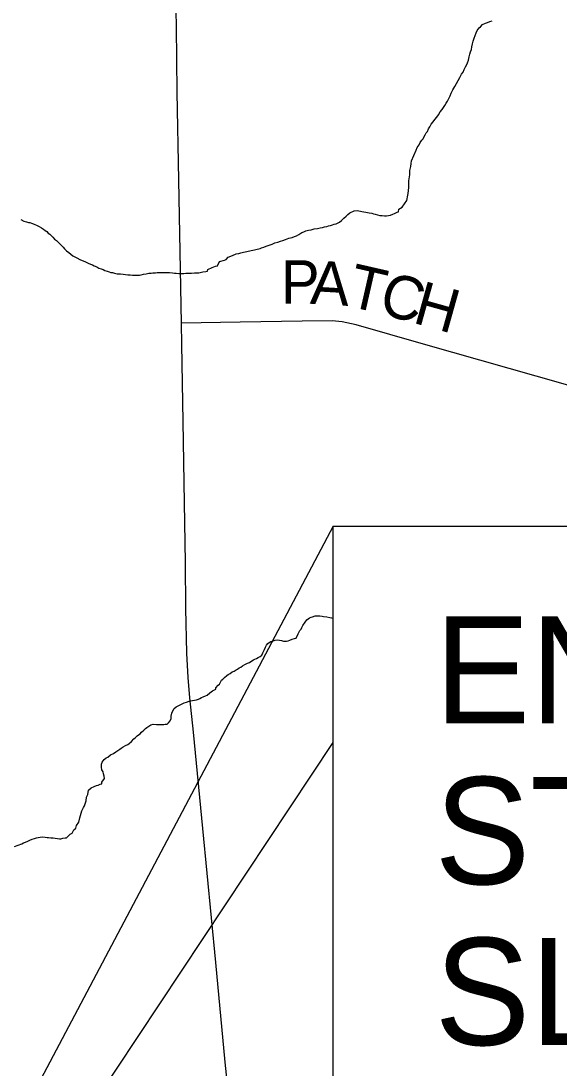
# Model space of a CAD drawing. Extents: x 0 to 34, y 0 to 22.
# Drawn here: x 6.59 to 7.293, y 17.696 to 19.063 of the extents above; entities that cross this region are included whole.
import ezdxf

# ---------------------------------------------------------------- set-up
doc = ezdxf.new("R2010")
doc.units = 0
for name, color, linetype in [('GM_X_Minor_River', 7, 'Continuous'), ('GM_X_State_Route', 7, 'Continuous'), ('GM_X_Township_Road', 7, 'Continuous'), ('GM_X_Township_Road_Text', 7, 'Continuous'), ('SH_Border', 7, 'Continuous'), ('SH_Text', 7, 'Continuous')]:
    doc.layers.add(name, color=color, linetype=linetype)

msp = doc.modelspace()

# ---------------------------------------------------------------- linework, layer by layer
at = {"layer": 'GM_X_Minor_River'}
for points in [[(7.1, 18.8803), (7.1062, 18.8941), (7.1076, 18.8976), (7.1102, 18.9014), (7.1116, 18.9041), (7.1135, 18.9072), (7.1153, 18.9091), (7.1164, 18.9114), (7.1179, 18.9141), (7.1194, 18.9168), (7.1208, 18.9187), (7.1223, 18.9222), (7.1241, 18.9249), (7.126, 18.928), (7.1282, 18.9311), (7.1304, 18.9342), (7.133, 18.9373), (7.1352, 18.9403), (7.1374, 18.9442), (7.14, 18.9473), (7.1419, 18.95), (7.1437, 18.9527), (7.1452, 18.9554), (7.147, 18.9581), (7.1485, 18.9608), (7.1507, 18.9654), (7.1521, 18.9688), (7.1543, 18.9731), (7.1565, 18.9773), (7.1591, 18.9811), (7.1609, 18.985), (7.1631, 18.9892), (7.1653, 18.9934), (7.1675, 18.9961), (7.169, 18.9996), (7.1708, 19.0031), (7.1722, 19.0061), (7.1733, 19.0084), (7.1744, 19.0119), (7.1755, 19.0161), (7.1765, 19.0195), (7.1772, 19.0226), (7.1783, 19.0256), (7.179, 19.0291), (7.18, 19.0333), (7.1807, 19.0367), (7.1818, 19.0405), (7.1847, 19.0474), (7.1861, 19.0505), (7.1883, 19.054), (7.1902, 19.0555), (7.1928, 19.0583), (7.197, 19.0602), (7.1996, 19.0611), (7.2026, 19.0623), (7.2056, 19.0631)], [(6.8052, 18.7337), (6.809, 18.7338), (6.8128, 18.7338), (6.8163, 18.7339), (6.8197, 18.734), (6.822, 18.734), (6.8273, 18.7353), (6.8314, 18.7358), (6.8333, 18.7362), (6.8341, 18.7385), (6.8397, 18.7409), (6.8438, 18.7429), (6.8465, 18.7433), (6.8494, 18.7487), (6.8555, 18.7507), (6.8577, 18.7515), (6.8607, 18.7543), (6.866, 18.7566), (6.8709, 18.7587), (6.8743, 18.7595), (6.877, 18.7603), (6.8804, 18.7611), (6.8826, 18.7616), (6.8887, 18.7628), (6.8906, 18.7633), (6.8929, 18.7637), (6.8951, 18.7641), (6.8985, 18.765), (6.9004, 18.7654), (6.9023, 18.7658), (6.9042, 18.7666), (6.9069, 18.7674), (6.9102, 18.769), (6.914, 18.7702), (6.9178, 18.7715), (6.9216, 18.7731), (6.9253, 18.7743), (6.9287, 18.7755), (6.9318, 18.7763), (6.9355, 18.7775), (6.9397, 18.7792), (6.9442, 18.7804), (6.9473, 18.7816), (6.9499, 18.7824), (6.9529, 18.784), (6.9567, 18.7867), (6.9593, 18.7876), (6.9619, 18.7888), (6.9653, 18.7896), (6.9691, 18.7904), (6.9729, 18.7917), (6.9771, 18.7921), (6.9809, 18.793), (6.9839, 18.7934), (6.9865, 18.7942), (6.9896, 18.7947), (6.9918, 18.7955), (6.9941, 18.7959), (6.9968, 18.7967), (6.999, 18.7975), (7.0017, 18.798), (7.0036, 18.7988), (7.0062, 18.8004), (7.0088, 18.8023), (7.0118, 18.8054), (7.0148, 18.8081), (7.017, 18.8101), (7.0196, 18.8124), (7.0253, 18.8148), (7.0295, 18.8153), (7.0352, 18.8143), (7.0402, 18.8132), (7.0447, 18.8126), (7.0482, 18.8119), (7.0505, 18.8112), (7.0528, 18.8105), (7.0555, 18.8098), (7.0585, 18.8091), (7.0616, 18.8088), (7.0646, 18.8085), (7.0673, 18.8085), (7.0699, 18.809), (7.0726, 18.8094), (7.0756, 18.8106), (7.0779, 18.8114), (7.0812, 18.8134), (7.0831, 18.8138), (7.0834, 18.8172), (7.0879, 18.82), (7.0939, 18.8285), (7.0952, 18.8353), (7.0959, 18.8376), (7.0965, 18.8453), (7.0968, 18.8494), (7.0967, 18.854), (7.0974, 18.8593), (7.0977, 18.862), (7.098, 18.8677), (7.099, 18.873), (7.0997, 18.8769), (7.1, 18.8803)], [(6.5896, 18.8035), (6.5934, 18.8017), (6.5969, 18.8006), (6.5996, 18.7999), (6.6015, 18.7996), (6.6034, 18.7988), (6.6072, 18.7974), (6.6107, 18.796), (6.6137, 18.7945), (6.6164, 18.7927), (6.6191, 18.7912), (6.6215, 18.7893), (6.6234, 18.7879), (6.6253, 18.786), (6.6273, 18.7845), (6.6292, 18.7827), (6.6315, 18.7808), (6.6335, 18.7782), (6.6362, 18.7764), (6.6428, 18.7697), (6.6448, 18.7674), (6.6467, 18.7652), (6.6494, 18.7626), (6.6521, 18.7604), (6.6548, 18.7582), (6.6575, 18.7563), (6.6618, 18.7541), (6.6675, 18.7512), (6.671, 18.7498), (6.6741, 18.7483), (6.6775, 18.7465), (6.6806, 18.7454), (6.6833, 18.7443), (6.6856, 18.7432), (6.6887, 18.7418), (6.6917, 18.7403), (6.6944, 18.7392), (6.6971, 18.7382), (6.6994, 18.7371), (6.7025, 18.7364), (6.7048, 18.7353), (6.7071, 18.7346), (6.7094, 18.7343), (6.712, 18.7335), (6.7155, 18.7329), (6.7197, 18.7326), (6.7235, 18.7323), (6.7262, 18.732), (6.7292, 18.7316), (6.7326, 18.7313), (6.7357, 18.731), (6.7387, 18.7311), (6.741, 18.7311), (6.7429, 18.7312), (6.7448, 18.7312), (6.7467, 18.7316), (6.7497, 18.7325), (6.7535, 18.7329), (6.7569, 18.7334), (6.76, 18.7334), (6.7619, 18.7339), (6.7638, 18.7339), (6.7657, 18.734), (6.7679, 18.7344), (6.7706, 18.7344), (6.7729, 18.7345), (6.7763, 18.7346), (6.7816, 18.7343), (6.7839, 18.7343), (6.7877, 18.734), (6.7904, 18.7337), (6.7927, 18.7334), (6.7961, 18.7331), (6.7988, 18.7332), (6.8007, 18.7332), (6.8026, 18.7332), (6.8052, 18.7337)], [(6.8534, 18.2034), (6.8557, 18.2054), (6.8586, 18.2081), (6.8605, 18.2093), (6.8632, 18.2109), (6.8658, 18.2128), (6.8684, 18.214), (6.871, 18.2156), (6.8729, 18.2164), (6.8748, 18.218), (6.8771, 18.2191), (6.8793, 18.2207), (6.8823, 18.2227), (6.8857, 18.2243), (6.8883, 18.2251), (6.8902, 18.2263), (6.8936, 18.2286), (6.8955, 18.2294), (6.8974, 18.2306), (6.8996, 18.2318), (6.9022, 18.233), (6.9045, 18.2349), (6.9059, 18.238), (6.9078, 18.2422), (6.9092, 18.2453), (6.9107, 18.2476), (6.9122, 18.2499), (6.914, 18.2511), (6.9163, 18.2527), (6.9193, 18.2535), (6.922, 18.2543), (6.925, 18.2548), (6.9277, 18.2544), (6.9303, 18.2537), (6.933, 18.253), (6.9368, 18.2531), (6.9387, 18.2535), (6.941, 18.2544), (6.944, 18.2556), (6.947, 18.2564), (6.9493, 18.2568), (6.9518, 18.2626), (6.954, 18.2668), (6.9559, 18.2687), (6.9566, 18.271), (6.9581, 18.2737), (6.961, 18.278), (6.9632, 18.2807), (6.9666, 18.2834), (6.9689, 18.2842), (6.9708, 18.285), (6.9742, 18.2859), (6.9772, 18.2859), (6.9802, 18.286), (6.9833, 18.2857), (6.9852, 18.2853), (6.9894, 18.285), (6.9932, 18.284), (6.9955, 18.2833), (6.9977, 18.2826)], [(6.6258, 17.9967), (6.6288, 17.9964), (6.6319, 17.9961), (6.6345, 17.9957), (6.6376, 17.9954), (6.6399, 17.9951), (6.6418, 17.9951), (6.6444, 17.9956), (6.6475, 17.996), (6.6494, 17.9961), (6.6542, 18.0011), (6.6568, 18.0023), (6.659, 18.0065), (6.6616, 18.0089), (6.6623, 18.0123), (6.6653, 18.0166), (6.6667, 18.0223), (6.6695, 18.0315), (6.6714, 18.0357), (6.6728, 18.038), (6.6739, 18.0418), (6.675, 18.0445), (6.6756, 18.0495), (6.6771, 18.0529), (6.6781, 18.0583), (6.6814, 18.0617), (6.6852, 18.0633), (6.6886, 18.0646), (6.6905, 18.065), (6.6931, 18.0662), (6.6954, 18.0666), (6.6954, 18.0689), (6.6987, 18.0739), (6.6986, 18.0769), (6.6974, 18.0796), (6.697, 18.0826), (6.6954, 18.0852), (6.695, 18.0883), (6.6949, 18.0905), (6.6949, 18.0924), (6.696, 18.0951), (6.6985, 18.0986), (6.7012, 18.1006), (6.7034, 18.1017), (6.7068, 18.1045), (6.7105, 18.1065), (6.7135, 18.1084), (6.7188, 18.112), (6.7207, 18.1131), (6.7233, 18.1151), (6.7263, 18.1167), (6.7293, 18.1183), (6.7312, 18.1195), (6.7342, 18.1222), (6.7372, 18.1253), (6.7394, 18.1272), (6.7416, 18.1292), (6.7435, 18.1307), (6.7454, 18.1319), (6.7472, 18.1342), (6.7502, 18.1366), (6.7525, 18.1389), (6.7543, 18.1401), (6.7596, 18.1436), (6.7626, 18.1448), (6.7668, 18.1442), (6.7702, 18.1442), (6.7733, 18.1443), (6.7763, 18.1444), (6.7782, 18.1448), (6.7809, 18.1448), (6.7827, 18.1464), (6.7846, 18.1491), (6.786, 18.1522), (6.786, 18.1552), (6.7867, 18.159), (6.7877, 18.1613), (6.7899, 18.1652), (6.7926, 18.1671), (6.7967, 18.1695), (6.8005, 18.1711), (6.8031, 18.1723), (6.8061, 18.1735), (6.8095, 18.1747), (6.8141, 18.1756), (6.8163, 18.176), (6.819, 18.1765), (6.8216, 18.1773), (6.8235, 18.1781), (6.8258, 18.1793), (6.828, 18.1805), (6.8307, 18.1817), (6.8329, 18.1825), (6.8367, 18.1856), (6.84, 18.1883), (6.8446, 18.1903), (6.8445, 18.1922), (6.8475, 18.1957), (6.8494, 18.1969), (6.8516, 18.2019), (6.8534, 18.2034)], [(6.5811, 17.9847), (6.591, 17.9883), (6.5932, 17.9895), (6.5958, 17.9907), (6.5989, 17.9919), (6.6015, 17.9931), (6.6045, 17.9943), (6.6075, 17.9952), (6.6102, 17.996), (6.6121, 17.9968), (6.6147, 17.9972), (6.6178, 17.9973), (6.6212, 17.997), (6.6239, 17.9967), (6.6258, 17.9967)]]:
    msp.add_lwpolyline(points, dxfattribs=at)
at = {"layer": 'GM_X_State_Route'}
msp.add_lwpolyline([(6.8618, 17.6536), (6.8567, 17.7033), (6.8444, 17.8334), (6.8276, 18.0085), (6.815, 18.1342), (6.8104, 18.179), (6.8082, 18.2057), (6.8064, 18.2374), (6.8053, 18.2959), (6.8047, 18.3559), (6.8033, 18.4335), (6.8018, 18.5398), (6.8, 18.6404), (6.7996, 18.6684), (6.7962, 18.8552), (6.794, 18.9701), (6.7928, 19.0553), (6.7911, 19.1392), (6.7891, 19.2487), (6.7865, 19.4262), (6.7831, 19.6111), (6.7814, 19.6976), (6.7808, 19.7315), (6.7797, 19.8052)], dxfattribs=at)
at = {"layer": 'GM_X_Township_Road'}
msp.add_lwpolyline([(7.7061, 18.4728), (7.6958, 18.4761), (7.6784, 18.4806), (7.6485, 18.4887), (7.5711, 18.5109), (7.4654, 18.5409), (7.3013, 18.588), (7.1156, 18.6408), (7.0279, 18.6662), (7.0095, 18.6699), (6.9963, 18.6713), (6.9571, 18.671), (6.8763, 18.6697), (6.7996, 18.6684)], dxfattribs=at)
at = {"layer": 'SH_Border'}
for points in [[(6.9977, 18.4031), (6.2611, 17.0116), (6.9977, 18.1206)], [(6.9977, 18.4031), (8.9734, 18.4031), (8.9734, 17.6552), (6.9977, 17.6552)]]:
    msp.add_lwpolyline(points, close=True, dxfattribs=at)

# ---------------------------------------------------------------- texts
at = {"layer": 'GM_X_Township_Road_Text'}
for s, rotation, p in [('P', 359.9097, (6.9294, 18.6937)), ('A', 356.6904, (6.9669, 18.6937)), ('T', 347.0895, (7.0143, 18.6911)), ('C', 344.484, (7.0551, 18.6818)), ('H', 344.3573, (7.1, 18.6693))]:
    msp.add_text(s, height=0.0568, rotation=rotation, dxfattribs=at).set_placement(p)
at = {"layer": 'SH_Text'}
for s, p in [('END ACQUISITION', (7.1303, 18.1456)), ('STA 640+21.90', (7.1303, 17.9356)), ('SLM 12.31', (7.1303, 17.7256))]:
    msp.add_text(s, height=0.14, dxfattribs=at).set_placement(p)

doc.saveas('drawing.dxf')
